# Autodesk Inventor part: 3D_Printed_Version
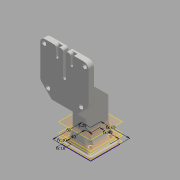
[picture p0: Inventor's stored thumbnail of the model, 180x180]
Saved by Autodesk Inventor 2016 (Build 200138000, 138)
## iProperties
Created: 2016-04
Part Number: 3D_Printed_Version
Material: Generic
Document SubType Name: Modeling
Designer: bongo_000
Density: 1 g/cm^3
Appearance: Default
Author: bongo_000
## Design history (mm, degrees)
sketch "Sketch1"
  geometry: L1 (0, 0)-(60, 0); L2 (60, 0)-(60, 60); L3 (60, 60)-(0, 60); L4 (0, 60)-(0, 0); C1 r 2.625 at (10, 50); C2 r 2.625 at (10, 10); C3 r 2.625 at (50, 10); C4 r 2.625 at (50, 50)
  constraints: 8 end point, 4 centre point, 3 equal radius, 2 horizontal alignment, 2 parallel, 2 vertical alignment, 1 horizontal, 1 perpendicular
  dimensions: "d0" = 40 distance of C1.centre C2.centre; "d1" = 5.25 diameter of C1; "d2" = 40 distance of C4.centre C1.centre (= d0); "d3" = 60 distance of L3.end L1.start; "d4" = 60 distance of L2.end L3.end (= d3); "d5" = 10 distance from line of L1 C2.centre (= -0.5 x d0 + 0.5 x d3); "d6" = 10 distance from line of L4 C2.centre (= d5)
workplane "Work Plane1"
sketch "Sketch2"
  geometry: L1 (60, 60)-(0, 60) reference; L2 (0, 60)-(0, 0) reference; L3 (0, 0)-(60, 0) reference; L4 (60, 0)-(60, 60) reference; L5 (15, 55)-(45, 55); L6 (45, 55)-(45, 5); L7 (45, 5)-(15, 5); L8 (15, 5)-(15, 55); 3 further points
  constraints: 8 end point, 2 midpoint, 2 parallel, 1 horizontal, 1 perpendicular, 1 vertical alignment
  dimensions: "d8" = 30 distance of L5.start L5.end; "d9" = 5 distance between parallel lines of L3 L7; "d10" = 5 distance between parallel lines of L1 L5 (= d9)
workplane "Work Plane2"
sketch "Sketch3"
  geometry: L1 (0, 60)-(0, 0) reference; L2 (60, 60)-(0, 60) reference; L3 (60, 0)-(60, 60) reference; L4 (0, 0)-(60, 0) reference; L5 (3, 57)-(3, 3); L6 (3, 3)-(57, 3); L7 (57, 3)-(57, 57); L8 (57, 57)-(3, 57); 1 further point
  constraints: 8 end point, 3 other
  dimensions: "d12" = 3 distance between parallel lines of L4 L6
workplane "Work Plane3"
sketch "Sketch4"
  geometry: L1 (3, 57)-(3, 3) reference; L2 (57, 57)-(3, 57) reference; L3 (57, 3)-(57, 57) reference; L4 (3, 3)-(57, 3) reference; L5 (11, 57)-(49, 57); L6 (49, 57)-(49, 3); L7 (49, 3)-(11, 3); L8 (11, 3)-(11, 57); L9 (11, 57)-(49, 57); L10 (49, 57)-(49, 3); L11 (49, 3)-(11, 3); L12 (11, 3)-(11, 57); 3 further points
  constraints: 16 end point, 4 midpoint, 4 parallel, 2 horizontal, 2 perpendicular
  dimensions: "d14" = 8 distance between parallel lines of L3 L6
extrude "Extrusion1" new body sketch "Sketch1" distance "d15" = 5; taper "d16" = 0 deg
loft "Loft1" dims "d17" = 0, "d18" = 90 deg, "d19" = 0, "d20" = 90 deg, "d21" = 0, "d22" = 90 deg
fillet "Fillet1" dims "d23" = 3
fillet "Fillet2" dims "d24" = 3
fillet "Fillet3" dims "d25" = 5
extrude "Extrusion2" cut sketch "Sketch1" stored distance "d26" = 5; taper "d27" = 0 deg
workplane "Work Plane4"
sketch "Sketch5"
  geometry: L1 (55, 60)-(5, 60) reference; L2 (60, 5)-(60, 55) reference; L3 (5, 0)-(55, 0) reference; L4 (0, 55)-(0, 5) reference; C1 r 2.625 at (50, 50) reference; C2 r 2.625 at (50, 10) reference; C3 r 2.625 at (10, 10) reference; C4 r 2.625 at (10, 50) reference; C5 r 5.125 at (10, 50); C6 r 5.125 at (10, 10); C7 r 5.125 at (50, 10); C8 r 5.125 at (50, 50); A1 r 5 centre (5, 55) between (5, 60) and (0, 55) reference; A2 r 5 centre (55, 55) between (60, 55) and (55, 60) reference; A3 r 5 centre (55, 5) between (55, 0) and (60, 5) reference; A4 r 5 centre (5, 5) between (0, 5) and (5, 0) reference; 1 further point
  constraints: 4 centre point, 3 equal radius
  dimensions: "d28" = 10.25 diameter of C8
extrude "Extrusion3" cut sketch "Sketch5" stored distance "d29" = 5; taper "d30" = 0 deg
sketch "Sketch7"
  geometry: L1 (25.025, -43.875)-(25.025, -6.125) reference; L2 (20.05, 0)-(0, 0) reference; L3 (-4.975, -6.125)-(-4.975, -43.875) reference; L4 (0, -50)-(20.05, -50) reference; L5 (0.025, 0)-(20.025, 0); L6 (25.025, -5)-(25.025, -45); L7 (20.025, -50)-(0.025, -50); L8 (-4.975, -45)-(-4.975, -5); A1 r 5.125 centre (30.025, -45) between (25.025, -43.875) and (24.96, -45.782) reference; A2 r 5.125 centre (30.025, -5) between (24.96, -4.218) and (25.025, -6.125) reference; A3 r 5.125 centre (-9.975, -5) between (-4.975, -6.125) and (-4.91, -4.218) reference; A4 r 5.125 centre (-9.975, -45) between (-4.91, -45.782) and (-4.975, -43.875) reference; A5 r 5 centre (0.025, -5) between (0.025, 0) and (-4.975, -5); A6 r 5 centre (20.025, -5) between (25.025, -5) and (20.025, 0); A7 r 5 centre (20.025, -45) between (20.025, -50) and (25.025, -45); A8 r 5 centre (0.025, -45) between (-4.975, -45) and (0.025, -50); 4 further points
  constraints: 8 end point, 8 point on circle, 8 tangent, 6 midpoint, 4 centre point, 3 equal radius, 2 parallel, 1 horizontal, 1 perpendicular, 4 other
  dimensions: "d34" = 5 radius of A5
extrude "Extrusion5" join sketch "Sketch7" distance "d35" = 135; taper "d36" = 0 deg
sketch "Sketch8"
  geometry: L1 (0, 0)-(20.05, 0) reference; L2 (20.05, 0)-(20.05, 135) reference; L3 (0, 135)-(20.05, 135) reference; L4 (0, 0)-(0, 135) reference; L5 (-39.975, 135)-(60.025, 135); L6 (60.025, 135)-(60.025, 55); L7 (60.025, 55)-(-39.975, 55); L8 (-39.975, 55)-(-39.975, 135); L9 (-39.975, 135)-(60.025, 135); L10 (60.025, 135)-(60.025, 155); L11 (60.025, 155)-(-39.975, 155); L12 (-39.975, 155)-(-39.975, 135); 2 further points
  constraints: 16 end point, 4 parallel, 2 horizontal, 2 midpoint, 2 perpendicular, 1 point on line
  dimensions: "d37" = 80 distance of L5.end L6.end; "d38" = 20 distance of L5.end L10.end; "d39" = 100 distance of L6.end L7.end
extrude "Extrusion6" join sketch "Sketch8" distance "d40" = 30; taper "d42" = 0 deg; dims "d41" = 10, "d43" = 0
sketch "Sketch10"
  geometry: L1 (0, 40)-(0, 0) reference; L2 (100, 0)-(0, 0) reference; L3 (100, 40)-(100, 0) reference; L4 (0, 40)-(100, 40) reference; L5 (-55, 30)-(0, 30) reference; L6 (-30, 30)-(0, 0); 1 further point
  constraints: 2 end point, 1 point on line
  dimensions: "d44" = 45 deg angle of L5 L6
extrude "Extrusion7" join sketch "Sketch10" stored distance "d45" = 20; taper "d46" = 0 deg
sketch "Sketch11"
  geometry: L1 (-4.975, -55)-(-4.975, -135) reference; L2 (-4.975, -55)-(-39.975, -55) reference; L3 (-39.975, -55)-(-39.975, -155) reference; L4 (-39.975, -155)-(60.025, -155) reference; L5 (60.025, -155)-(60.025, -55) reference; L6 (60.025, -55)-(25.025, -55) reference; L7 (25.025, -135)-(25.025, -55) reference; L8 (-4.975, -135)-(25.025, -135) reference; 1 further point
extrude "Extrusion8" cut sketch "Sketch11" stored distance "d47" = 20; taper "d48" = 0 deg
sketch "Sketch12"
  geometry: L1 (30, 0)-(30, 5) reference; L2 (25.025, 0)-(30, 0) reference; L3 (0, 5)-(0, 0) reference; L4 (0, 0)-(4.975, 0) reference; A1 r 5 centre (25, 5) between (28.914, 1.889) and (30, 5) reference; A2 r 5 centre (5, 5) between (0, 5) and (1.086, 1.889) reference; 1 further point
  constraints: 2 other
extrude "Extrusion9" join sketch "Sketch12" stored distance "d49" = 20; taper "d50" = 0 deg
sketch "Sketch13"
  geometry: L1 (65, 130)-(65, 20) reference; L2 (35, 20)-(65, 20) reference; L3 (35, 20)-(35, 130) reference; L4 (0, 130)-(35, 130) reference; L5 (0, 0)-(0, 130) reference; L6 (100, 0)-(0, 0) reference; L7 (100, 130)-(100, 0) reference; L8 (65, 130)-(100, 130) reference; 1 further point
extrude "Extrusion10" cut sketch "Sketch13" distance "d51" = 18; taper "d52" = 0 deg
sketch "Sketch14"
  geometry: L1 (25.025, -5)-(25.025, -68) reference; L2 (20.05, 0)-(0, 0) reference; L3 (-4.975, -5)-(-4.975, -68) reference; L4 (-4.975, -68)-(25.025, -68) reference; A1 r 5 centre (20.025, -5) between (25.025, -5) and (23.939, -1.889) reference; A2 r 5 centre (0.025, -5) between (-3.889, -1.889) and (-4.975, -5) reference; 1 further point
  constraints: 2 other
extrude "Extrusion11" cut sketch "Sketch14" distance "d53" = 50; taper "d54" = 0 deg
sketch "Sketch15"
  geometry: L1 (-85, 38.875)-(-85, -24.125) reference; L2 (-85, -24.125)-(-43, -24.125) reference; L3 (-20, -1.125)-(-43, -24.125) reference; L4 (0, -1.125)-(-20, -1.125) reference; L5 (0, -1.125)-(0, 0) reference; L6 (0, 0)-(0, 37.75) reference; L7 (0, 37.75)-(0, 38.875) reference; L8 (0, 38.875)-(-85, 38.875) reference; L9 (-85, 38.875)-(-85, -24.125) reference; L10 (-85, 0.875)-(-27, 58.875); L11 (-27, 58.875)-(-85, 58.875); L12 (0, 38.875)-(-85, 38.875) reference; L13 (-85, 58.875)-(-85, 38.875); 1 further point
  constraints: 6 end point, 1 perpendicular, 1 point on line, 1 vertical
  dimensions: "d55" = 20 distance between parallel lines of L8 L11; "d56" = 45 deg angle of L1 L10; "d57" = 25 distance from line of L2 L10.start
extrude "Extrusion12" cut sketch "Sketch15" stored distance "d58" = 50; taper "d59" = 0 deg
sketch "Sketch16"
  geometry: L1 (35, 112)-(35, 70) reference; L2 (0, 112)-(35, 112) reference; L3 (0, 0)-(0, 112) reference; L4 (100, 0)-(0, 0) reference; L5 (100, 112)-(100, 0) reference; L6 (65, 112)-(100, 112) reference; L7 (65, 70)-(65, 112) reference; L8 (65, 112)-(100, 77); L9 (0, 112)-(35, 112) reference; L10 (35, 112)-(0, 77); L11 (65, 70)-(35, 70) reference; 1 further point
  constraints: 4 end point, 2 point on line
  dimensions: "d61" = 45 deg angle of L2 L10; "d62" = 45 deg angle of L6 L8 (= d61)
extrude "Extrusion13" cut sketch "Sketch16" stored distance "d63" = 50; taper "d64" = 0 deg
fillet "Fillet5" dims "d65" = 10
chamfer "Chamfer1" distance "d66" = 30; stored, may be unused: second distance "d67" = 2, angle "d68" = 45 deg
fillet "Fillet6" dims "d69" = 10
fillet "Fillet7" dims "d70" = 10
sketch "Sketch17"
  geometry: L1 (-39.975, 145)-(-39.975, 82.142) reference; L2 (-37.046, 75.071)-(-16.975, 55) reference; L3 (-16.975, 55)-(37.025, 55) reference; L4 (37.025, 55)-(57.096, 75.071) reference; L5 (60.025, 82.142)-(60.025, 145) reference; L6 (50.025, 155)-(-29.975, 155) reference; C1 r 2.75 at (-31.975, 147); C2 r 2.75 at (52.025, 147); C3 r 2.75 at (-31.975, 63); C4 r 2.75 at (52.025, 63); C5 r 2.75 at (-23.975, 71); C6 r 2.75 at (44.025, 71); A1 r 10 centre (-29.975, 145) between (-29.975, 155) and (-39.975, 145) reference; A2 r 10 centre (-29.975, 82.142) between (-39.975, 82.142) and (-37.046, 75.071) reference; A3 r 10 centre (50.025, 82.142) between (57.096, 75.071) and (60.025, 82.142) reference; A4 r 10 centre (50.025, 145) between (60.025, 145) and (50.025, 155) reference; 1 further point
  constraints: 6 centre point, 5 equal radius, 3 horizontal alignment, 2 vertical alignment
  dimensions: "d71" = 84 distance of C1.centre C2.centre; "d72" = 5.5 diameter of C2; "d73" = 8 distance from line of L1 C1.centre; "d74" = 8 distance from line of L6 C1.centre (= d73); "d75" = 84 distance of C1.centre C3.centre (= d71); "d76" = 8 horizontal distance of C3.centre C5.centre; "d77" = 8 horizontal distance of C3.centre C5.centre (= d76); "d78" = 8 horizontal distance of C4.centre C6.centre (= d77)
extrude "Extrusion14" cut sketch "Sketch17" stored distance "d79" = 50; taper "d80" = 0 deg
sketch "Sketch18"
  geometry: L1 (-39.975, 145)-(-39.975, 82.142) reference; L2 (-37.046, 75.071)-(-16.975, 55) reference; L3 (-16.975, 55)-(37.025, 55) reference; L4 (37.025, 55)-(57.096, 75.071) reference; L5 (60.025, 82.142)-(60.025, 145) reference; L6 (50.025, 155)-(-29.975, 155) reference; L7 (-19.85, 68.618)-(-23.975, 66.237); L8 (-23.975, 66.237)-(-28.1, 68.618); L9 (-28.1, 68.618)-(-28.1, 73.382); L10 (-28.1, 73.382)-(-23.975, 75.763); L11 (-23.975, 75.763)-(-19.85, 73.382); L12 (-19.85, 73.382)-(-19.85, 68.618); L13 (-31.975, 142.237)-(-36.1, 144.618); L14 (-36.1, 144.618)-(-36.1, 149.382); L15 (-36.1, 149.382)-(-31.975, 151.763); L16 (-31.975, 151.763)-(-27.85, 149.382); L17 (-27.85, 149.382)-(-27.85, 144.618); L18 (-27.85, 144.618)-(-31.975, 142.237); L19 (52.025, 142.237)-(47.9, 144.618); L20 (47.9, 144.618)-(47.9, 149.382); L21 (47.9, 149.382)-(52.025, 151.763); L22 (52.025, 151.763)-(56.15, 149.382); L23 (56.15, 149.382)-(56.15, 144.618); L24 (56.15, 144.618)-(52.025, 142.237); L25 (44.025, 66.237)-(39.9, 68.618); L26 (39.9, 68.618)-(39.9, 73.382); L27 (39.9, 73.382)-(44.025, 75.763); L28 (44.025, 75.763)-(48.15, 73.382); L29 (48.15, 73.382)-(48.15, 68.618); L30 (48.15, 68.618)-(44.025, 66.237); C1 r 2.75 at (-23.975, 71) reference; C2 r 2.75 at (-31.975, 147) reference; C3 r 2.75 at (52.025, 147) reference; C4 r 2.75 at (44.025, 71) reference; A1 r 10 centre (-29.975, 145) between (-29.975, 155) and (-39.975, 145) reference; A2 r 10 centre (-29.975, 82.142) between (-39.975, 82.142) and (-37.046, 75.071) reference; A3 r 10 centre (50.025, 82.142) between (57.096, 75.071) and (60.025, 82.142) reference; A4 r 10 centre (50.025, 145) between (60.025, 145) and (50.025, 155) reference; 5 further points
  constraints: 48 end point, 4 coincident, 4 vertical, 3 parallel, 52 other
  dimensions: "d81" = 8.25 distance between parallel lines of L14 L17
extrude "Extrusion15" cut sketch "Sketch18" distance "d82" = 7; taper "d83" = 0 deg
workplane "Work Plane5"
sketch "Sketch19"
  geometry: C1 r 2.75 at (-42.309, -16) reference; C2 r 2.75 at (-42.309, -84) reference; C3 r 6 at (-42.309, -16); C4 r 6 at (-42.309, -84); 1 further point
  constraints: 2 centre point, 1 equal radius
  dimensions: "d85" = 12 diameter of C3
extrude "Extrusion16" cut sketch "Sketch19" stored distance "d86" = 7; taper "d87" = 0 deg
sketch "Sketch20"
  geometry: L1 (56.15, 144.618)-(52.025, 142.237) reference; L2 (52.025, 142.237)-(47.9, 144.618) reference; L3 (47.9, 144.618)-(47.9, 149.382) reference; L4 (47.9, 149.382)-(52.025, 151.763) reference; L5 (52.025, 151.763)-(56.15, 149.382) reference; L6 (56.15, 149.382)-(56.15, 144.618) reference; L7 (-19.85, 73.382)-(-19.85, 68.618) reference; L8 (-19.85, 68.618)-(-23.975, 66.237) reference; L9 (-23.975, 66.237)-(-28.1, 68.618) reference; L10 (-28.1, 68.618)-(-28.1, 73.382) reference; L11 (-28.1, 73.382)-(-23.975, 75.763) reference; L12 (-23.975, 75.763)-(-19.85, 73.382) reference; L13 (-27.85, 144.618)-(-31.975, 142.237) reference; L14 (-31.975, 142.237)-(-36.1, 144.618) reference; L15 (-36.1, 144.618)-(-36.1, 149.382) reference; L16 (-36.1, 149.382)-(-31.975, 151.763) reference; L17 (-31.975, 151.763)-(-27.85, 149.382) reference; L18 (-27.85, 149.382)-(-27.85, 144.618) reference; L19 (48.15, 68.618)-(44.025, 66.237) reference; L20 (44.025, 66.237)-(39.9, 68.618) reference; L21 (39.9, 68.618)-(39.9, 73.382) reference; L22 (39.9, 73.382)-(44.025, 75.763) reference; L23 (44.025, 75.763)-(48.15, 73.382) reference; L24 (48.15, 73.382)-(48.15, 68.618) reference; L25 (-39.975, 145)-(-39.975, 82.142) reference; L26 (-37.046, 75.071)-(-16.975, 55) reference; L27 (-16.975, 55)-(37.025, 55) reference; L28 (37.025, 55)-(57.096, 75.071) reference; L29 (60.025, 82.142)-(60.025, 145) reference; L30 (50.025, 155)-(-29.975, 155) reference; L31 (7.275, 105)-(7.275, 155); L32 (12.775, 105)-(12.775, 155); L33 (7.275, 155)-(12.775, 155); A1 r 10 centre (-29.975, 145) between (-29.975, 155) and (-39.975, 145) reference; A2 r 10 centre (-29.975, 82.142) between (-39.975, 82.142) and (-37.046, 75.071) reference; A3 r 10 centre (50.025, 82.142) between (57.096, 75.071) and (60.025, 82.142) reference; A4 r 10 centre (50.025, 145) between (60.025, 145) and (50.025, 155) reference; A5 r 2.75 centre (10.025, 105) between (7.275, 105) and (12.775, 105); 2 further points
  constraints: 6 end point, 2 point on circle, 2 point on line, 2 tangent, 2 vertical, 1 centre point, 1 collinear, 1 midpoint, 1 vertical alignment
  dimensions: "d88" = 5.5 diameter of A5; "d89" = 50 distance from line of L30 A5.centre
extrude "Extrusion17" cut sketch "Sketch20" stored distance "d90" = 7; taper "d91" = 0 deg
sketch "Sketch21"
  geometry: L1 (7.275, 105)-(7.275, 155) reference; L2 (7.275, 155)-(-29.975, 155) reference; L3 (-39.975, 145)-(-39.975, 82.142) reference; L4 (-37.046, 75.071)-(-16.975, 55) reference; L5 (-16.975, 55)-(37.025, 55) reference; L6 (37.025, 55)-(57.096, 75.071) reference; L7 (60.025, 82.142)-(60.025, 145) reference; L8 (50.025, 155)-(12.775, 155) reference; L9 (12.775, 155)-(12.775, 105) reference; L10 (56.15, 144.618)-(52.025, 142.237) reference; L11 (52.025, 142.237)-(47.9, 144.618) reference; L12 (47.9, 144.618)-(47.9, 149.382) reference; L13 (47.9, 149.382)-(52.025, 151.763) reference; L14 (52.025, 151.763)-(56.15, 149.382) reference; L15 (56.15, 149.382)-(56.15, 144.618) reference; L16 (-19.85, 73.382)-(-19.85, 68.618) reference; L17 (-19.85, 68.618)-(-23.975, 66.237) reference; L18 (-23.975, 66.237)-(-28.1, 68.618) reference; L19 (-28.1, 68.618)-(-28.1, 73.382) reference; L20 (-28.1, 73.382)-(-23.975, 75.763) reference; L21 (-23.975, 75.763)-(-19.85, 73.382) reference; L22 (-27.85, 144.618)-(-31.975, 142.237) reference; L23 (-31.975, 142.237)-(-36.1, 144.618) reference; L24 (-36.1, 144.618)-(-36.1, 149.382) reference; L25 (-36.1, 149.382)-(-31.975, 151.763) reference; L26 (-31.975, 151.763)-(-27.85, 149.382) reference; L27 (-27.85, 149.382)-(-27.85, 144.618) reference; L28 (48.15, 68.618)-(44.025, 66.237) reference; L29 (44.025, 66.237)-(39.9, 68.618) reference; L30 (39.9, 68.618)-(39.9, 73.382) reference; L31 (39.9, 73.382)-(44.025, 75.763) reference; L32 (44.025, 75.763)-(48.15, 73.382) reference; L33 (48.15, 73.382)-(48.15, 68.618) reference; L34 (-85.473, 26.644)-(88.749, 26.644); L35 (88.749, 26.644)-(88.749, 198.324); L36 (88.749, 198.324)-(-85.473, 198.324); L37 (-85.473, 198.324)-(-85.473, 26.644); A1 r 10 centre (-29.975, 145) between (-29.975, 155) and (-39.975, 145) reference; A2 r 10 centre (-29.975, 82.142) between (-39.975, 82.142) and (-37.046, 75.071) reference; A3 r 10 centre (50.025, 82.142) between (57.096, 75.071) and (60.025, 82.142) reference; A4 r 10 centre (50.025, 145) between (60.025, 145) and (50.025, 155) reference; A5 r 2.75 centre (10.025, 105) between (7.275, 105) and (12.775, 105) reference; 1 further point
  constraints: 8 end point, 2 parallel, 1 horizontal, 1 perpendicular
extrude "Extrusion18" cut sketch "Sketch21" distance "d92" = 1; taper "d93" = 0 deg
fillet "Fillet8" dims "d94" = 4
sketch "Sketch22"
  geometry: L1 (52.025, 142.237)-(56.15, 144.618) reference; L2 (47.9, 144.618)-(52.025, 142.237) reference; L3 (47.9, 149.382)-(47.9, 144.618) reference; L4 (52.025, 151.763)-(47.9, 149.382) reference; L5 (56.15, 149.382)-(52.025, 151.763) reference; L6 (56.15, 144.618)-(56.15, 149.382) reference; L7 (-19.85, 68.618)-(-19.85, 73.382) reference; L8 (-23.975, 66.237)-(-19.85, 68.618) reference; L9 (-28.1, 68.618)-(-23.975, 66.237) reference; L10 (-28.1, 73.382)-(-28.1, 68.618) reference; L11 (-23.975, 75.763)-(-28.1, 73.382) reference; L12 (-19.85, 73.382)-(-23.975, 75.763) reference; L13 (-31.975, 142.237)-(-27.85, 144.618) reference; L14 (-36.1, 144.618)-(-31.975, 142.237) reference; L15 (-36.1, 149.382)-(-36.1, 144.618) reference; L16 (-31.975, 151.763)-(-36.1, 149.382) reference; L17 (-27.85, 149.382)-(-31.975, 151.763) reference; L18 (-27.85, 144.618)-(-27.85, 149.382) reference; L19 (44.025, 66.237)-(48.15, 68.618) reference; L20 (39.9, 68.618)-(44.025, 66.237) reference; L21 (39.9, 73.382)-(39.9, 68.618) reference; L22 (44.025, 75.763)-(39.9, 73.382) reference; L23 (48.15, 73.382)-(44.025, 75.763) reference; L24 (48.15, 68.618)-(48.15, 73.382) reference; L25 (12.775, 105)-(12.775, 151) reference; L26 (7.275, 151)-(7.275, 105) reference; L27 (-29.975, 155)-(3.275, 155) reference; L28 (-39.975, 82.142)-(-39.975, 145) reference; L29 (-15.975, 54)-(-37.046, 75.071) reference; L30 (36.025, 54)-(-15.975, 54) reference; L31 (57.096, 75.071)-(36.025, 54) reference; L32 (60.025, 145)-(60.025, 82.142) reference; L33 (16.775, 155)-(50.025, 155) reference; L34 (-7.225, 135)-(-7.225, 155); L35 (-2.725, 135)-(-2.725, 155); L36 (22.775, 135)-(22.775, 155); L37 (27.275, 135)-(27.275, 155); L38 (16.775, 155)-(50.025, 155) reference; L39 (-7.225, 155)-(-2.725, 155); L40 (3.275, 155)-(-29.975, 155) reference; L41 (22.775, 155)-(27.275, 155); A1 r 4 centre (16.775, 151) between (16.775, 155) and (12.775, 151) reference; A2 r 2.75 centre (10.025, 105) between (7.275, 105) and (12.775, 105) reference; A3 r 4 centre (3.275, 151) between (7.275, 151) and (3.275, 155) reference; A4 r 10 centre (-29.975, 145) between (-29.975, 155) and (-39.975, 145) reference; A5 r 10 centre (-29.975, 82.142) between (-39.975, 82.142) and (-37.046, 75.071) reference; A6 r 10 centre (50.025, 82.142) between (57.096, 75.071) and (60.025, 82.142) reference; A7 r 10 centre (50.025, 145) between (60.025, 145) and (50.025, 155) reference; A8 r 2.25 centre (-4.975, 135) between (-7.225, 135) and (-2.725, 135); A9 r 2.25 centre (25.025, 135) between (22.775, 135) and (27.275, 135); 1 further point
  constraints: 12 end point, 4 point on circle, 4 point on line, 4 tangent, 4 vertical, 2 centre point, 2 collinear, 1 equal radius, 1 horizontal alignment
  dimensions: "d95" = 4.5 diameter of A9; "d96" = 15 horizontal distance of A2.centre A9.centre; "d97" = 15 horizontal distance of A2.centre A8.centre (= d96); "d98" = 20 distance from line of L38 A9.centre
extrude "Extrusion19" cut sketch "Sketch22" distance "d99" = 7; taper "d100" = 0 deg
fillet "Fillet9" dims "d101" = 4
body "Solid1"
node "Projected Loop1"
node "Projected Loop3"
node "Projected Loop4"
node "Projected Loop6"
node "Projected Loop7"
node "Projected Loop8"
node "Projected Loop9"
node "Projected Loop10"
node "Projected Loop11"
node "Projected Loop12"
node "Projected Loop13"
node "Projected Loop14"
node "Projected Loop15"
node "Projected Loop16"
node "Projected Loop17"
node "Projected Loop18"
other parameters: "d11" = 5, "d31" = -5, "d84" = 0
